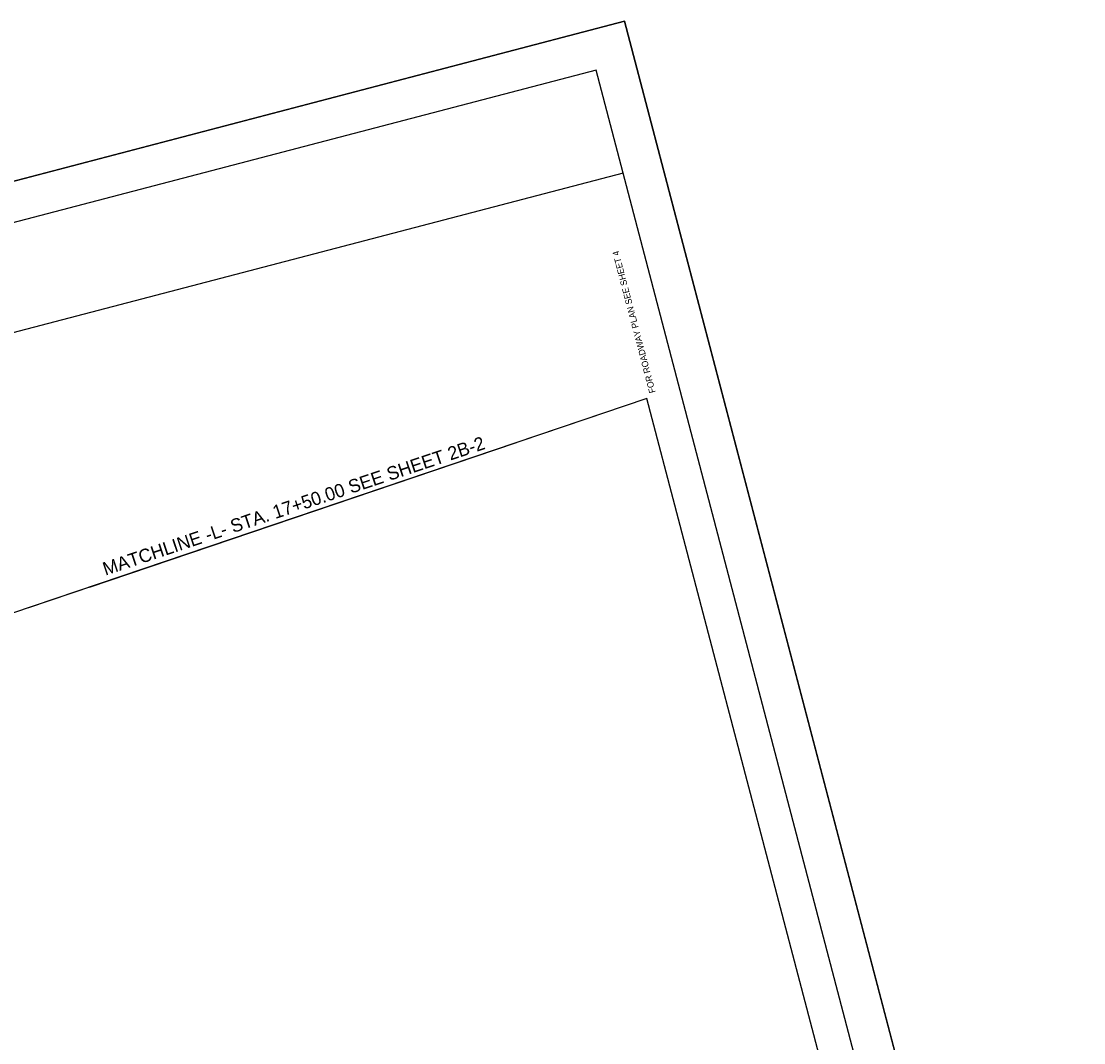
# Model space of a CAD drawing. Extents: x 1366699 to 1368206, y 878140 to 880064.
# Drawn here: x 1367209 to 1368206, y 879105 to 880064 of the extents above; entities that cross this region are included whole.
import ezdxf

# ---------------------------------------------------------------- set-up
doc = ezdxf.new("R2010")
doc.units = 0
for name, color, linetype in [('Prop Conc 4in Sidewalk', 7, 'Continuous'), ('Prop Dimension', 7, 'Continuous'), ('Prop Shade Medium', 7, 'Continuous'), ('Sheet_Plot_Border_Outside_CELL', 7, 'Continuous'), ('Sheet_Title_Block_Text', 7, 'Continuous'), ('Typical Shoulder Slope CELL', 7, 'Continuous'), ('Typical Terminator CELL', 7, 'Continuous')]:
    doc.layers.add(name, color=color, linetype=linetype)

msp = doc.modelspace()

# ---------------------------------------------------------------- linework, layer by layer
at = {"layer": 'Prop Conc 4in Sidewalk'}
msp.add_line((1367272.7, 879532.45), (1367673.52, 879668.17), dxfattribs=at)
at = {"layer": 'Prop Shade Medium'}
for p, q in [((1367748.14, 880017.97), (1366756.62, 879758.15)), ((1368160.09, 878446.06), (1367748.14, 880017.97)), ((1367773.49, 879921.24), (1366781.97, 879661.42))]:
    msp.add_line(p, q, dxfattribs=at)
at = {"layer": 'Sheet_Plot_Border_Outside_CELL'}
msp.add_line((1367215.67, 879513.13), (1367758.31, 879696.89), dxfattribs=at)
msp.add_lwpolyline([(1366869.99, 879396.08), (1367149.56, 878329.29), (1367149.56, 878329.29), (1368092.87, 878576.5), (1368092.87, 878576.5), (1367795.92, 879709.62)], close=True, dxfattribs=at)
at = {"layer": 'Sheet_Title_Block_Text'}
for p, q in [((1367774.9, 880063.78), (1366710.84, 879784.92)), ((1368205.86, 878419.32), (1367774.9, 880063.78))]:
    msp.add_line(p, q, dxfattribs=at)
at = {"layer": 'Typical Terminator CELL'}
msp.add_lwpolyline([(1367141.8, 878140.46), (1366710.84, 879784.92), (1367774.9, 880063.78), (1368205.86, 878419.32)], close=True, dxfattribs=at)

# ---------------------------------------------------------------- texts
at = {"layer": 'Prop Dimension'}
msp.add_text('MATCHLINE -L- STA. 17+50.00 SEE SHEET 2B-2', height=12.5, rotation=18.46336, dxfattribs=at).set_placement((1367287.63, 879543.11))
at = {"layer": 'Typical Shoulder Slope CELL'}
msp.add_text('FOR ROADWAY PLAN SEE SHEET 4', height=6, rotation=104.68512, dxfattribs=at).set_placement((1367804.07, 879715.47))

doc.saveas('drawing.dxf')
